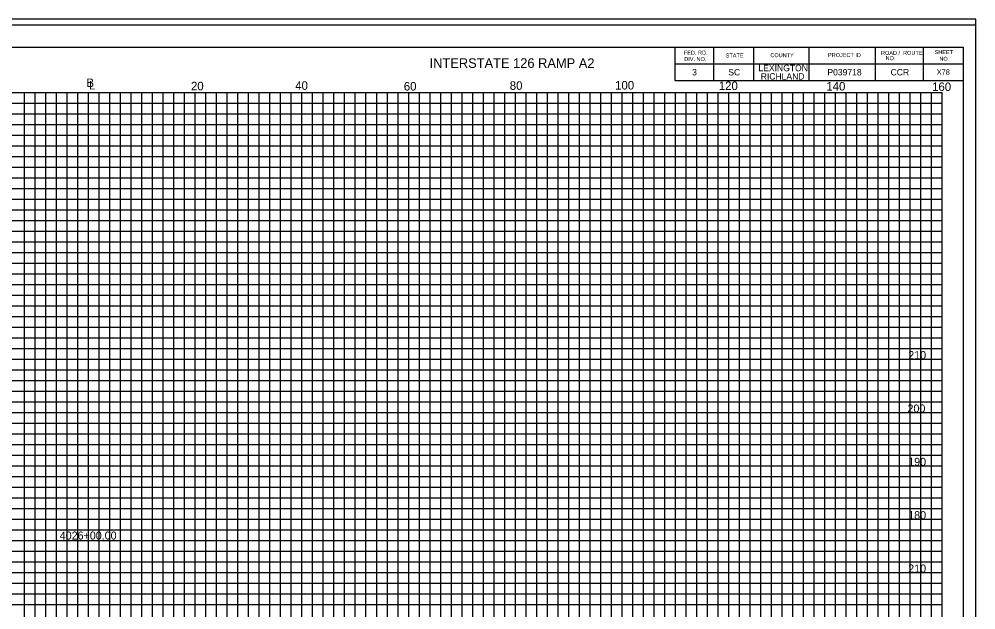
# Model space of a CAD drawing. Extents: x 967 to 1326, y 964 to 2584.
# Drawn here: x 1147 to 1326.3, y 1913 to 2023.7 of the extents above; entities that cross this region are included whole.
import ezdxf

# ---------------------------------------------------------------- set-up
doc = ezdxf.new("R2010")
doc.units = 0
for name, color, linetype in [('Default', 7, 'Continuous'), ('RD_SHT_Bndy', 7, 'Continuous'), ('RD_SHT_IplotShp', 7, 'Continuous'), ('RD_SHT_MjGrid', 7, 'Continuous'), ('RD_SHT_MnGrid', 7, 'Continuous'), ('RD_SHT_TX', 7, 'Continuous'), ('RD_Sketch1', 7, 'Continuous')]:
    doc.layers.add(name, color=color, linetype=linetype)

msp = doc.modelspace()

# ---------------------------------------------------------------- linework, layer by layer
at = {"layer": 'RD_SHT_Bndy'}
for p, q in [((996.11, 2018.46), (1323.89, 2018.46)), ((1269.89, 2018.46), (1269.89, 2012.21)), ((1277.14, 2018.46), (1277.14, 2012.21)), ((1284.64, 2018.46), (1284.64, 2012.21)), ((1295, 2018.46), (1295, 2012.21)), ((1307.43, 2018.46), (1307.43, 2012.21)), ((1316.39, 2018.46), (1316.39, 2012.21)), ((1323.89, 2018.46), (1323.89, 1808.98)), ((1269.89, 2015.33), (1323.89, 2015.33)), ((1269.89, 2012.21), (1323.89, 2012.21))]:
    msp.add_line(p, q, dxfattribs=at)
at = {"layer": 'RD_SHT_IplotShp'}
for points in [[(967.41, 1803.72), (1326.28, 1803.72), (1326.28, 2023.72), (967.41, 2023.72)], [(988.52, 1804.84), (1326.28, 1804.84), (1326.28, 2022.6), (988.52, 2022.6)]]:
    msp.add_lwpolyline(points, close=True, dxfattribs=at)
at = {"layer": 'RD_SHT_MjGrid'}
for p, q in [((1000, 2010), (1320, 2010)), ((1150, 1840), (1150, 2010)), ((1160, 1840), (1160, 2010)), ((1170, 1840), (1170, 2010)), ((1180, 1840), (1180, 2010)), ((1190, 1840), (1190, 2010)), ((1200, 1840), (1200, 2010)), ((1210, 1840), (1210, 2010)), ((1220, 1840), (1220, 2010)), ((1230, 1840), (1230, 2010)), ((1240, 1840), (1240, 2010)), ((1250, 1840), (1250, 2010)), ((1260, 1840), (1260, 2010)), ((1270, 1840), (1270, 2010)), ((1280, 1840), (1280, 2010)), ((1290, 1840), (1290, 2010)), ((1300, 1840), (1300, 2010)), ((1310, 1840), (1310, 2010)), ((1320, 1840), (1320, 2010)), ((1000, 2000), (1320, 2000)), ((1000, 1990), (1320, 1990)), ((1000, 1980), (1320, 1980)), ((1000, 1970), (1320, 1970)), ((1000, 1960), (1320, 1960)), ((1000, 1950), (1320, 1950)), ((1000, 1940), (1320, 1940)), ((1000, 1930), (1320, 1930)), ((1000, 1920), (1320, 1920))]:
    msp.add_line(p, q, dxfattribs=at)
at = {"layer": 'RD_SHT_MnGrid'}
for p, q in [((1148, 1840), (1148, 2010)), ((1152, 1840), (1152, 2010)), ((1154, 1840), (1154, 2010)), ((1156, 1840), (1156, 2010)), ((1158, 1840), (1158, 2010)), ((1162, 1840), (1162, 2010)), ((1164, 1840), (1164, 2010)), ((1166, 1840), (1166, 2010)), ((1168, 1840), (1168, 2010)), ((1172, 1840), (1172, 2010)), ((1174, 1840), (1174, 2010)), ((1176, 1840), (1176, 2010)), ((1178, 1840), (1178, 2010)), ((1182, 1840), (1182, 2010)), ((1184, 1840), (1184, 2010)), ((1186, 1840), (1186, 2010)), ((1188, 1840), (1188, 2010)), ((1192, 1840), (1192, 2010)), ((1194, 1840), (1194, 2010)), ((1196, 1840), (1196, 2010)), ((1198, 1840), (1198, 2010)), ((1202, 1840), (1202, 2010)), ((1204, 1840), (1204, 2010)), ((1206, 1840), (1206, 2010)), ((1208, 1840), (1208, 2010)), ((1212, 1840), (1212, 2010)), ((1214, 1840), (1214, 2010)), ((1216, 1840), (1216, 2010)), ((1218, 1840), (1218, 2010)), ((1222, 1840), (1222, 2010)), ((1224, 1840), (1224, 2010)), ((1226, 1840), (1226, 2010)), ((1228, 1840), (1228, 2010)), ((1232, 1840), (1232, 2010)), ((1234, 1840), (1234, 2010)), ((1236, 1840), (1236, 2010)), ((1238, 1840), (1238, 2010)), ((1242, 1840), (1242, 2010)), ((1244, 1840), (1244, 2010)), ((1246, 1840), (1246, 2010)), ((1248, 1840), (1248, 2010)), ((1252, 1840), (1252, 2010)), ((1254, 1840), (1254, 2010)), ((1256, 1840), (1256, 2010)), ((1258, 1840), (1258, 2010)), ((1262, 1840), (1262, 2010)), ((1264, 1840), (1264, 2010)), ((1266, 1840), (1266, 2010)), ((1268, 1840), (1268, 2010)), ((1272, 1840), (1272, 2010)), ((1274, 1840), (1274, 2010)), ((1276, 1840), (1276, 2010)), ((1278, 1840), (1278, 2010)), ((1282, 1840), (1282, 2010)), ((1284, 1840), (1284, 2010)), ((1286, 1840), (1286, 2010)), ((1288, 1840), (1288, 2010)), ((1292, 1840), (1292, 2010)), ((1294, 1840), (1294, 2010)), ((1296, 1840), (1296, 2010)), ((1298, 1840), (1298, 2010)), ((1302, 1840), (1302, 2010)), ((1304, 1840), (1304, 2010)), ((1306, 1840), (1306, 2010)), ((1308, 1840), (1308, 2010)), ((1312, 1840), (1312, 2010)), ((1314, 1840), (1314, 2010)), ((1316, 1840), (1316, 2010)), ((1318, 1840), (1318, 2010)), ((1000, 2008), (1320, 2008)), ((1000, 2006), (1320, 2006)), ((1000, 2004), (1320, 2004)), ((1000, 2002), (1320, 2002)), ((1000, 1998), (1320, 1998)), ((1000, 1996), (1320, 1996)), ((1000, 1994), (1320, 1994)), ((1000, 1992), (1320, 1992)), ((1000, 1988), (1320, 1988)), ((1000, 1986), (1320, 1986)), ((1000, 1984), (1320, 1984)), ((1000, 1982), (1320, 1982)), ((1000, 1978), (1320, 1978)), ((1000, 1976), (1320, 1976)), ((1000, 1974), (1320, 1974)), ((1000, 1972), (1320, 1972)), ((1000, 1968), (1320, 1968)), ((1000, 1966), (1320, 1966)), ((1000, 1964), (1320, 1964)), ((1000, 1962), (1320, 1962)), ((1000, 1958), (1320, 1958)), ((1000, 1956), (1320, 1956)), ((1000, 1954), (1320, 1954)), ((1000, 1952), (1320, 1952)), ((1000, 1948), (1320, 1948)), ((1000, 1946), (1320, 1946)), ((1000, 1944), (1320, 1944)), ((1000, 1942), (1320, 1942)), ((1000, 1938), (1320, 1938)), ((1000, 1936), (1320, 1936)), ((1000, 1934), (1320, 1934)), ((1000, 1932), (1320, 1932)), ((1000, 1928), (1320, 1928)), ((1000, 1926), (1320, 1926)), ((1000, 1924), (1320, 1924)), ((1000, 1922), (1320, 1922)), ((1000, 1918), (1320, 1918)), ((1000, 1916), (1320, 1916)), ((1000, 1914), (1320, 1914))]:
    msp.add_line(p, q, dxfattribs=at)
at = {"layer": 'RD_Sketch1'}
msp.add_lwpolyline([(967.41, 1803.72), (1326.28, 1803.72), (1326.28, 2023.72), (967.41, 2023.72)], close=True, dxfattribs=at)

# ---------------------------------------------------------------- texts
at = {"layer": 'Default'}
for s, height, p in [('X78', 1, (1318.95, 2013.3)), ('210', 1.5, (1313.61, 1960)), ('200', 1.5, (1313.47, 1950)), ('190', 1.5, (1313.61, 1940)), ('180', 1.5, (1313.61, 1930)), ('4026+00.00', 1.5, (1154.61, 1926.18)), ('210', 1.5, (1313.61, 1920))]:
    msp.add_text(s, height=height, dxfattribs=at).set_placement(p)
at = {"layer": 'RD_SHT_TX'}
for s, height, p in [('FED. RD.', 0.75, (1271.58, 2017.05)), ('STATE', 0.75, (1279.41, 2016.53)), ('COUNTY', 0.75, (1287.78, 2016.59)), ('PROJECT ID', 0.75, (1298.58, 2016.63)), ('ROAD /  ROUTE', 0.75, (1308.51, 2017.01)), ('SHEET', 0.75, (1318.56, 2017.16)), ('DIV. NO.', 0.75, (1271.64, 2015.86)), ('LEXINGTON', 1.2, (1285.54, 2013.96)), ('   NO.', 0.75, (1308.51, 2016.03)), ('NO.', 0.75, (1319.45, 2015.91)), ('3', 1.2, (1273.12, 2013.17)), ('SC', 1.2, (1279.89, 2013.17)), ('RICHLAND', 1.2, (1285.97, 2012.39)), ('P039718', 1.2, (1298.46, 2013.17)), ('CCR', 1.2, (1310.31, 2013.17)), ('B', 1.6, (1159.61, 2010.99)), ('L', 1.6, (1160.12, 2010.54)), ('20', 1.6, (1179.2, 2010.38)), ('40', 1.6, (1198.74, 2010.47)), ('60', 1.6, (1219.08, 2010.33)), ('80', 1.6, (1238.94, 2010.47)), ('100', 1.6, (1258.67, 2010.53)), ('120', 1.6, (1278.11, 2010.43)), ('140', 1.6, (1298.26, 2010.34)), ('160', 1.6, (1318.08, 2010.25))]:
    msp.add_text(s, height=height, dxfattribs=at).set_placement(p)
msp.add_text('INTERSTATE 126 RAMP A2', height=1.8, rotation=0, dxfattribs=at).set_placement((1223.92, 2014.58))

doc.saveas('drawing.dxf')
